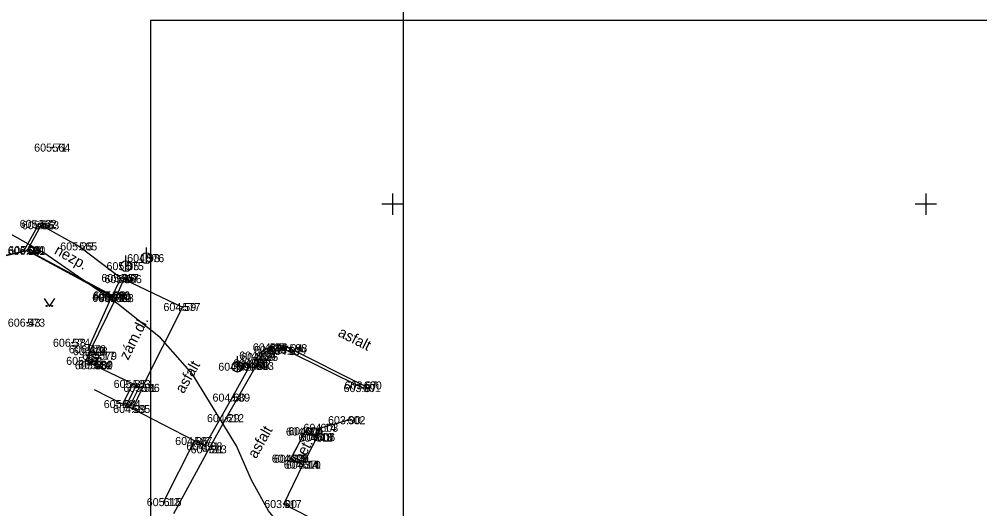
# Model space of a CAD drawing. Extents: x -844765 to -843273, y -997542 to -995529.
# Drawn here: x -843585 to -843494.9, y -997278.6 to -997232.7 of the extents above; entities that cross this region are included whole.
import ezdxf

# ---------------------------------------------------------------- set-up
doc = ezdxf.new("R2010")
doc.units = 0
for name, color, linetype in [('Benešův rám', 7, 'Continuous'), ('Betonový strop', 7, 'Continuous'), ('Dno', 7, 'Continuous'), ('Doplněk polohopisu', 7, 'Continuous'), ('Klenba', 7, 'Continuous'), ('Osa', 7, 'Continuous'), ('Rámeček', 7, 'Continuous'), ('Sítě podzemní nerozlišené', 7, 'Continuous'), ('Vrstva 63', 7, 'Continuous'), ('Výška', 7, 'Continuous'), ('Číslo bodu', 7, 'Continuous'), ('Řezy', 7, 'Continuous')]:
    doc.layers.add(name, color=color, linetype=linetype)

msp = doc.modelspace()

# ---------------------------------------------------------------- linework, layer by layer
at = {"layer": 'Benešův rám'}
msp.add_line((-843576.24, -997258.56), (-843575.92, -997258.82), dxfattribs=at)
for points in [[(-843575.92, -997258.82), (-843578.36, -997263.79), (-843578.74, -997264.7)], [(-843578.51, -997263.61), (-843576.3, -997258.66), (-843576.24, -997258.56)], [(-843570.49, -997279.01), (-843567.2, -997272.99), (-843565.58, -997270.07), (-843562.78, -997265.18), (-843563.22, -997264.93), (-843565.01, -997268.14), (-843567.6, -997272.71), (-843568.54, -997272.21)]]:
    msp.add_lwpolyline(points, dxfattribs=at)
at = {"layer": 'Betonový strop'}
for p, q in [((-843583.14, -997251.86), (-843584.552, -997254.39)), ((-843577.78, -997264.813), (-843578.615, -997264.4)), ((-843577.635, -997264.516), (-843578.487, -997264.095)), ((-843577.49, -997264.22), (-843578.36, -997263.79)), ((-843577.93, -997265.12), (-843577.49, -997264.22)), ((-843577.93, -997265.12), (-843578.74, -997264.7)), ((-843574.33, -997266.86), (-843577.93, -997265.12)), ((-843574.956, -997268.907), (-843574.016, -997266.997)), ((-843574.663, -997269.058), (-843573.713, -997267.128)), ((-843574.37, -997269.21), (-843573.412, -997267.263)), ((-843573.412, -997267.263), (-843573.48, -997267.23))]:
    msp.add_line(p, q, dxfattribs=at)
for points in [[(-843584.21, -997254.31), (-843582.91, -997251.99), (-843583.14, -997251.86)], [(-843582.91, -997251.99), (-843579.34, -997253.97), (-843575.45, -997256.93)], [(-843590.56, -997259.11), (-843589.27, -997256.78), (-843588.36, -997255.6), (-843586.7, -997254.89), (-843584.21, -997254.31), (-843576.24, -997258.56)], [(-843576.3, -997258.66), (-843584.21, -997254.4), (-843586.73, -997254.99), (-843588.3, -997255.64), (-843589.2, -997256.81), (-843590.49, -997259.15)], [(-843575.92, -997258.82), (-843575.16, -997257.04), (-843575.45, -997256.93), (-843576.24, -997258.56)], [(-843575.16, -997257.04), (-843569.66, -997259.65), (-843573.48, -997267.23)], [(-843559.65, -997263.51), (-843552.67, -997267)], [(-843577.93, -997265.12), (-843577.87, -997265.06), (-843577.49, -997264.22)], [(-843563.06, -997265.03), (-843562.56, -997264.2)], [(-843562.38, -997264.34), (-843562.78, -997265.18)], [(-843552.76, -997267.25), (-843559.76, -997263.78)], [(-843575.26, -997268.75), (-843574.33, -997266.86), (-843573.48, -997267.23)], [(-843557.04, -997271.85), (-843558.18, -997271.29), (-843559.53, -997273.88), (-843558.39, -997274.44)], [(-843558.39, -997274.42), (-843559.51, -997273.86), (-843558.15, -997271.33), (-843557.09, -997271.9)]]:
    msp.add_lwpolyline(points, dxfattribs=at)
for centre, radius, start, end in [((-843560.671, -997265.686), 2.404, 64.86792, 141.81058), ((-843560.717, -997265.71), 2.154, 63.61279, 140.51698)]:
    msp.add_arc(centre, radius, start, end, dxfattribs=at)
at = {"layer": 'Dno'}
msp.add_lwpolyline([(-843582.65, -997258.849), (-843582.15, -997259.599), (-843581.65, -997258.849)], dxfattribs=at)
for centre in [(-843582.4, -997259.549), (-843581.9, -997259.549)]:
    msp.add_circle(centre, 0.05, dxfattribs=at)
at = {"layer": 'Doplněk polohopisu'}
for p, q in [((-843573.06, -997255.57), (-843573.06, -997254.07)), ((-843574.97, -997256.32), (-843574.97, -997254.82)), ((-843564.52, -997265.75), (-843564.52, -997264.25))]:
    msp.add_line(p, q, dxfattribs=at)
for centre in [(-843573.06, -997255.07), (-843574.97, -997255.82), (-843564.52, -997265.25)]:
    msp.add_circle(centre, 0.5, dxfattribs=at)
at = {"layer": 'Klenba'}
for p, q in [((-843577.937, -997267.395), (-843575.26, -997268.75)), ((-843574.37, -997269.21), (-843575.26, -997268.75)), ((-843568.54, -997272.21), (-843574.37, -997269.21)), ((-843556.75, -997270.97), (-843554.2, -997270.26)), ((-843558.39, -997274.44), (-843557.04, -997271.85)), ((-843557.04, -997271.85), (-843556.75, -997270.97)), ((-843571.44, -997277.94), (-843568.54, -997272.21)), ((-843560.18, -997278.12), (-843558.39, -997274.44)), ((-843554.71, -997280.92), (-843560.18, -997278.12))]:
    msp.add_line(p, q, dxfattribs=at)
at = {"layer": 'Osa'}
msp.add_lwpolyline([(-843488.74, -997327.355), (-843502.42, -997320.345), (-843503.72, -997319.36), (-843508.85, -997314.12), (-843519.095, -997304.575), (-843522.13, -997301.975), (-843525.755, -997299.515), (-843535.535, -997294.28), (-843547.175, -997288.35), (-843559.45, -997281.385), (-843561.605, -997278.77), (-843563.2, -997275.885), (-843564.61, -997272.67), (-843568.725, -997265.945), (-843571.745, -997262.55), (-843575.655, -997259.4), (-843582.66, -997254.57), (-843594.613, -997247.845), (-843607.165, -997241.295), (-843613.085, -997237.56), (-843629.39, -997225.885), (-843652.733, -997208.733), (-843685.02, -997184.17)], dxfattribs=at)
at = {"layer": 'Rámeček'}
for p, q in [((-843550, -997249), (-843550, -997251)), ((-843500, -997249), (-843500, -997251)), ((-843549, -997250), (-843551, -997250)), ((-843499, -997250), (-843501, -997250))]:
    msp.add_line(p, q, dxfattribs=at)
at = {"layer": 'Sítě podzemní nerozlišené'}
for p, q in [((-843581.87, -997244.71), (-843581.92, -997244.66)), ((-843581.87, -997244.71), (-843581.92, -997244.76)), ((-843581.87, -997244.71), (-843581.82, -997244.66)), ((-843581.87, -997244.71), (-843581.82, -997244.76)), ((-843583.14, -997251.86), (-843583.19, -997251.81)), ((-843583.14, -997251.86), (-843583.19, -997251.91)), ((-843583.14, -997251.86), (-843583.09, -997251.81)), ((-843583.14, -997251.86), (-843583.09, -997251.91)), ((-843582.91, -997251.99), (-843582.96, -997251.94)), ((-843582.91, -997251.99), (-843582.96, -997252.04)), ((-843582.91, -997251.99), (-843582.86, -997251.94)), ((-843582.91, -997251.99), (-843582.86, -997252.04)), ((-843584.21, -997254.31), (-843584.26, -997254.26)), ((-843584.21, -997254.31), (-843584.26, -997254.36)), ((-843584.21, -997254.4), (-843584.26, -997254.35)), ((-843584.21, -997254.4), (-843584.26, -997254.45)), ((-843584.21, -997254.31), (-843584.16, -997254.26)), ((-843584.21, -997254.31), (-843584.16, -997254.36)), ((-843584.21, -997254.4), (-843584.16, -997254.35)), ((-843584.21, -997254.4), (-843584.16, -997254.45)), ((-843579.34, -997253.97), (-843579.39, -997253.92)), ((-843579.34, -997253.97), (-843579.39, -997254.02)), ((-843579.34, -997253.97), (-843579.29, -997253.92)), ((-843579.34, -997253.97), (-843579.29, -997254.02)), ((-843573.06, -997255.07), (-843573.11, -997255.02)), ((-843573.06, -997255.07), (-843573.11, -997255.12)), ((-843573.06, -997255.07), (-843573.01, -997255.02)), ((-843573.06, -997255.07), (-843573.01, -997255.12)), ((-843574.97, -997255.82), (-843575.02, -997255.77)), ((-843574.97, -997255.82), (-843575.02, -997255.87)), ((-843574.97, -997255.82), (-843574.92, -997255.77)), ((-843574.97, -997255.82), (-843574.92, -997255.87)), ((-843575.45, -997256.93), (-843575.5, -997256.88)), ((-843575.45, -997256.93), (-843575.5, -997256.98)), ((-843575.45, -997256.93), (-843575.4, -997256.88)), ((-843575.45, -997256.93), (-843575.4, -997256.98)), ((-843575.16, -997257.04), (-843575.21, -997256.99)), ((-843575.16, -997257.04), (-843575.21, -997257.09)), ((-843575.16, -997257.04), (-843575.11, -997256.99)), ((-843575.16, -997257.04), (-843575.11, -997257.09)), ((-843576.34, -997258.8), (-843576.39, -997258.75)), ((-843576.34, -997258.8), (-843576.39, -997258.85)), ((-843576.3, -997258.66), (-843576.35, -997258.61)), ((-843576.3, -997258.66), (-843576.35, -997258.71)), ((-843576.34, -997258.8), (-843576.29, -997258.75)), ((-843576.34, -997258.8), (-843576.29, -997258.85)), ((-843576.3, -997258.66), (-843576.25, -997258.61)), ((-843576.3, -997258.66), (-843576.25, -997258.71)), ((-843576.24, -997258.56), (-843576.29, -997258.51)), ((-843576.24, -997258.56), (-843576.29, -997258.61)), ((-843576.24, -997258.56), (-843576.19, -997258.51)), ((-843576.24, -997258.56), (-843576.19, -997258.61)), ((-843575.92, -997258.82), (-843575.97, -997258.77)), ((-843575.92, -997258.82), (-843575.97, -997258.87)), ((-843575.92, -997258.82), (-843575.87, -997258.77)), ((-843575.92, -997258.82), (-843575.87, -997258.87)), ((-843569.66, -997259.65), (-843569.71, -997259.6)), ((-843569.66, -997259.65), (-843569.71, -997259.7)), ((-843569.66, -997259.65), (-843569.61, -997259.6)), ((-843569.66, -997259.65), (-843569.61, -997259.7)), ((-843584.23, -997261.12), (-843584.28, -997261.07)), ((-843584.23, -997261.12), (-843584.28, -997261.17)), ((-843584.23, -997261.12), (-843584.18, -997261.07)), ((-843584.23, -997261.12), (-843584.18, -997261.17)), ((-843580, -997263), (-843580.05, -997262.95)), ((-843580, -997263), (-843580.05, -997263.05)), ((-843580, -997263), (-843579.95, -997262.95)), ((-843580, -997263), (-843579.95, -997263.05)), ((-843578.51, -997263.61), (-843578.56, -997263.56)), ((-843578.51, -997263.61), (-843578.56, -997263.66)), ((-843578.51, -997263.61), (-843578.46, -997263.56)), ((-843578.51, -997263.61), (-843578.46, -997263.66)), ((-843578.36, -997263.79), (-843578.41, -997263.74)), ((-843578.36, -997263.79), (-843578.31, -997263.74)), ((-843561.5, -997263.43), (-843561.55, -997263.38)), ((-843561.5, -997263.43), (-843561.55, -997263.48)), ((-843561.5, -997263.43), (-843561.45, -997263.38)), ((-843561.5, -997263.43), (-843561.45, -997263.48)), ((-843561.38, -997263.66), (-843561.43, -997263.61)), ((-843561.38, -997263.66), (-843561.43, -997263.71)), ((-843561.38, -997263.66), (-843561.33, -997263.61)), ((-843561.38, -997263.66), (-843561.33, -997263.71)), ((-843559.76, -997263.78), (-843559.81, -997263.73)), ((-843559.76, -997263.78), (-843559.71, -997263.73)), ((-843559.65, -997263.51), (-843559.7, -997263.46)), ((-843559.65, -997263.51), (-843559.7, -997263.56)), ((-843559.65, -997263.51), (-843559.6, -997263.46)), ((-843559.65, -997263.51), (-843559.6, -997263.56)), ((-843578.74, -997264.7), (-843578.79, -997264.65)), ((-843578.74, -997264.7), (-843578.69, -997264.65)), ((-843578.36, -997263.79), (-843578.41, -997263.84)), ((-843578.36, -997263.79), (-843578.31, -997263.84)), ((-843577.49, -997264.22), (-843577.54, -997264.17)), ((-843577.49, -997264.22), (-843577.54, -997264.27)), ((-843577.49, -997264.22), (-843577.44, -997264.17)), ((-843577.49, -997264.22), (-843577.44, -997264.27)), ((-843562.56, -997264.2), (-843562.61, -997264.15)), ((-843562.56, -997264.2), (-843562.61, -997264.25)), ((-843562.56, -997264.2), (-843562.51, -997264.15)), ((-843562.56, -997264.2), (-843562.51, -997264.25)), ((-843562.38, -997264.34), (-843562.43, -997264.29)), ((-843562.38, -997264.34), (-843562.43, -997264.39)), ((-843562.38, -997264.34), (-843562.33, -997264.29)), ((-843562.38, -997264.34), (-843562.33, -997264.39)), ((-843559.76, -997263.78), (-843559.81, -997263.83)), ((-843559.76, -997263.78), (-843559.71, -997263.83)), ((-843578.74, -997264.7), (-843578.79, -997264.75)), ((-843578.74, -997264.7), (-843578.69, -997264.75)), ((-843577.93, -997265.12), (-843577.98, -997265.07)), ((-843577.93, -997265.12), (-843577.98, -997265.17)), ((-843577.93, -997265.12), (-843577.88, -997265.07)), ((-843577.93, -997265.12), (-843577.88, -997265.17)), ((-843577.87, -997265.06), (-843577.92, -997265.01)), ((-843577.87, -997265.06), (-843577.92, -997265.11)), ((-843577.87, -997265.06), (-843577.82, -997265.01)), ((-843577.87, -997265.06), (-843577.82, -997265.11)), ((-843564.52, -997265.25), (-843564.57, -997265.2)), ((-843564.52, -997265.25), (-843564.57, -997265.3)), ((-843564.52, -997265.25), (-843564.47, -997265.2)), ((-843564.52, -997265.25), (-843564.47, -997265.3)), ((-843563.22, -997264.93), (-843563.27, -997264.88)), ((-843563.22, -997264.93), (-843563.27, -997264.98)), ((-843563.22, -997264.93), (-843563.17, -997264.88)), ((-843563.22, -997264.93), (-843563.17, -997264.98)), ((-843563.06, -997265.03), (-843563.11, -997264.98)), ((-843563.06, -997265.03), (-843563.11, -997265.08)), ((-843563.06, -997265.03), (-843563.01, -997264.98)), ((-843563.06, -997265.03), (-843563.01, -997265.08)), ((-843562.78, -997265.18), (-843562.83, -997265.13)), ((-843562.78, -997265.18), (-843562.83, -997265.23)), ((-843562.78, -997265.18), (-843562.73, -997265.13)), ((-843562.78, -997265.18), (-843562.73, -997265.23)), ((-843574.33, -997266.86), (-843574.38, -997266.81)), ((-843574.33, -997266.86), (-843574.38, -997266.91)), ((-843574.33, -997266.86), (-843574.28, -997266.81)), ((-843574.33, -997266.86), (-843574.28, -997266.91)), ((-843573.48, -997267.23), (-843573.53, -997267.18)), ((-843573.48, -997267.23), (-843573.53, -997267.28)), ((-843573.48, -997267.23), (-843573.43, -997267.18)), ((-843573.48, -997267.23), (-843573.43, -997267.28)), ((-843552.76, -997267.25), (-843552.81, -997267.2)), ((-843552.76, -997267.25), (-843552.81, -997267.3)), ((-843552.76, -997267.25), (-843552.71, -997267.2)), ((-843552.76, -997267.25), (-843552.71, -997267.3)), ((-843552.67, -997267), (-843552.72, -997266.95)), ((-843552.67, -997267), (-843552.72, -997267.05)), ((-843552.67, -997267), (-843552.62, -997266.95)), ((-843552.67, -997267), (-843552.62, -997267.05)), ((-843565.01, -997268.14), (-843565.06, -997268.09)), ((-843565.01, -997268.14), (-843565.06, -997268.19)), ((-843565.01, -997268.14), (-843564.96, -997268.09)), ((-843565.01, -997268.14), (-843564.96, -997268.19)), ((-843575.26, -997268.75), (-843575.31, -997268.7)), ((-843575.26, -997268.75), (-843575.31, -997268.8)), ((-843575.26, -997268.75), (-843575.21, -997268.7)), ((-843575.26, -997268.75), (-843575.21, -997268.8)), ((-843574.37, -997269.21), (-843574.42, -997269.16)), ((-843574.37, -997269.21), (-843574.32, -997269.16)), ((-843574.37, -997269.21), (-843574.42, -997269.26)), ((-843574.37, -997269.21), (-843574.32, -997269.26)), ((-843565.58, -997270.07), (-843565.63, -997270.02)), ((-843565.58, -997270.07), (-843565.53, -997270.02)), ((-843565.58, -997270.07), (-843565.63, -997270.12)), ((-843565.58, -997270.07), (-843565.53, -997270.12)), ((-843556.75, -997270.97), (-843556.8, -997270.92)), ((-843556.75, -997270.97), (-843556.7, -997270.92)), ((-843554.2, -997270.26), (-843554.25, -997270.21)), ((-843554.2, -997270.26), (-843554.25, -997270.31)), ((-843554.2, -997270.26), (-843554.15, -997270.21)), ((-843554.2, -997270.26), (-843554.15, -997270.31)), ((-843558.18, -997271.29), (-843558.23, -997271.24)), ((-843558.18, -997271.29), (-843558.23, -997271.34)), ((-843558.15, -997271.33), (-843558.2, -997271.28)), ((-843558.15, -997271.33), (-843558.2, -997271.38)), ((-843558.18, -997271.29), (-843558.13, -997271.24)), ((-843558.18, -997271.29), (-843558.13, -997271.34)), ((-843558.15, -997271.33), (-843558.1, -997271.28)), ((-843558.15, -997271.33), (-843558.1, -997271.38)), ((-843557.09, -997271.9), (-843557.14, -997271.85)), ((-843557.04, -997271.85), (-843557.09, -997271.8)), ((-843557.04, -997271.85), (-843557.09, -997271.9)), ((-843557.09, -997271.9), (-843557.04, -997271.85)), ((-843557.04, -997271.85), (-843556.99, -997271.8)), ((-843557.04, -997271.85), (-843556.99, -997271.9)), ((-843556.75, -997270.97), (-843556.8, -997271.02)), ((-843556.75, -997270.97), (-843556.7, -997271.02)), ((-843568.54, -997272.21), (-843568.59, -997272.16)), ((-843568.54, -997272.21), (-843568.59, -997272.26)), ((-843568.54, -997272.21), (-843568.49, -997272.16)), ((-843568.54, -997272.21), (-843568.49, -997272.26)), ((-843567.6, -997272.71), (-843567.65, -997272.66)), ((-843567.6, -997272.71), (-843567.65, -997272.76)), ((-843567.6, -997272.71), (-843567.55, -997272.66)), ((-843567.6, -997272.71), (-843567.55, -997272.76)), ((-843557.09, -997271.9), (-843557.14, -997271.95)), ((-843557.09, -997271.9), (-843557.04, -997271.95)), ((-843567.2, -997272.99), (-843567.25, -997272.94)), ((-843567.2, -997272.99), (-843567.25, -997273.04)), ((-843567.2, -997272.99), (-843567.15, -997272.94)), ((-843567.2, -997272.99), (-843567.15, -997273.04)), ((-843559.53, -997273.88), (-843559.58, -997273.83)), ((-843559.53, -997273.88), (-843559.58, -997273.93)), ((-843559.51, -997273.86), (-843559.56, -997273.81)), ((-843559.51, -997273.86), (-843559.56, -997273.91)), ((-843559.53, -997273.88), (-843559.48, -997273.83)), ((-843559.53, -997273.88), (-843559.48, -997273.93)), ((-843559.51, -997273.86), (-843559.46, -997273.81)), ((-843559.51, -997273.86), (-843559.46, -997273.91)), ((-843558.39, -997274.42), (-843558.44, -997274.37)), ((-843558.39, -997274.44), (-843558.44, -997274.39)), ((-843558.39, -997274.42), (-843558.44, -997274.47)), ((-843558.39, -997274.44), (-843558.44, -997274.49)), ((-843558.39, -997274.42), (-843558.34, -997274.37)), ((-843558.39, -997274.44), (-843558.34, -997274.39)), ((-843558.39, -997274.42), (-843558.34, -997274.47)), ((-843558.39, -997274.44), (-843558.34, -997274.49)), ((-843571.44, -997277.94), (-843571.49, -997277.89)), ((-843571.44, -997277.94), (-843571.49, -997277.99)), ((-843571.44, -997277.94), (-843571.39, -997277.89)), ((-843571.44, -997277.94), (-843571.39, -997277.99)), ((-843560.18, -997278.12), (-843560.23, -997278.07)), ((-843560.18, -997278.12), (-843560.23, -997278.17)), ((-843560.18, -997278.12), (-843560.13, -997278.07)), ((-843560.18, -997278.12), (-843560.13, -997278.17))]:
    msp.add_line(p, q, dxfattribs=at)
at = {"layer": 'Vrstva 63'}
for points in [[(-843738.967, -997297.121), (-843548.967, -997297.121), (-843548.967, -997154.621), (-843738.967, -997154.621)], [(-843572.683, -997375.3), (-843382.683, -997375.3), (-843382.683, -997232.8), (-843572.683, -997232.8)]]:
    msp.add_lwpolyline(points, close=True, dxfattribs=at)

# ---------------------------------------------------------------- texts
at = {"layer": 'Výška'}
for s, rotation, p in [('nezp.', 330.96502, (-843581.763, -997254.616)), ('zám.dl.', 63.25382, (-843574.772, -997264.695)), ('asfalt', 333.43495, (-843555.178, -997262.345)), ('asfalt', 60.45805, (-843569.567, -997267.83)), ('asfalt', 60.45805, (-843562.772, -997273.935)), ('bet.', 62.46987, (-843558.441, -997274.312))]:
    msp.add_text(s, height=1, rotation=rotation, dxfattribs=at).set_placement(p)
at = {"layer": 'Číslo bodu'}
for s, p in [('564', (-843581.87, -997245.085)), ('562', (-843583.14, -997252.235)), ('563', (-843582.91, -997252.365)), ('565', (-843579.34, -997254.345)), ('560', (-843584.21, -997254.685)), ('561', (-843584.21, -997254.775)), ('576', (-843573.06, -997255.445)), ('575', (-843574.97, -997256.195)), ('567', (-843575.45, -997257.305)), ('566', (-843575.16, -997257.415)), ('570', (-843576.3, -997259.035)), ('569', (-843576.24, -997258.935)), ('571', (-843576.34, -997259.175)), ('568', (-843575.92, -997259.195)), ('577', (-843569.66, -997260.025)), ('573', (-843584.23, -997261.495)), ('574', (-843580, -997263.375)), ('572', (-843578.51, -997263.985)), ('578', (-843578.36, -997264.165)), ('596', (-843561.5, -997263.805)), ('597', (-843561.38, -997264.035)), ('599', (-843559.76, -997264.155)), ('598', (-843559.65, -997263.885)), ('581', (-843578.74, -997265.075)), ('579', (-843577.49, -997264.595)), ('591', (-843563.22, -997265.305)), ('592', (-843563.06, -997265.405)), ('594', (-843562.56, -997264.575)), ('595', (-843562.38, -997264.715)), ('582', (-843577.93, -997265.495)), ('580', (-843577.87, -997265.435)), ('590', (-843564.52, -997265.625)), ('593', (-843562.78, -997265.555)), ('583', (-843574.33, -997267.235)), ('586', (-843573.48, -997267.605)), ('601', (-843552.76, -997267.625)), ('600', (-843552.67, -997267.375)), ('589', (-843565.01, -997268.515)), ('584', (-843575.26, -997269.125)), ('585', (-843574.37, -997269.585)), ('612', (-843565.58, -997270.445)), ('602', (-843554.2, -997270.635)), ('604', (-843558.18, -997271.665)), ('605', (-843558.15, -997271.705)), ('603', (-843556.75, -997271.345)), ('587', (-843568.54, -997272.585)), ('607', (-843557.09, -997272.275)), ('606', (-843557.04, -997272.225)), ('588', (-843567.6, -997273.085)), ('613', (-843567.2, -997273.365)), ('608', (-843559.53, -997274.255)), ('609', (-843559.51, -997274.235)), ('611', (-843558.39, -997274.795)), ('610', (-843558.39, -997274.815)), ('615', (-843571.44, -997278.315)), ('617', (-843560.18, -997278.495))]:
    msp.add_text(s, height=0.75, dxfattribs=at).set_placement(p)
at = {"layer": 'Řezy'}
for s, p in [('605.71', (-843583.577, -997245.085)), ('605.57', (-843584.935, -997252.235)), ('605.56', (-843584.726, -997252.365)), ('605.25', (-843581.135, -997254.345)), ('606.04', (-843586.058, -997254.775)), ('605.94', (-843586.008, -997254.685)), ('604.98', (-843574.858, -997255.445)), ('605.05', (-843576.798, -997256.195)), ('605.05', (-843577.278, -997257.305)), ('605.04', (-843576.988, -997257.415)), ('605.39', (-843578.098, -997259.035)), ('605.23', (-843578.035, -997258.935)), ('605.75', (-843578.135, -997259.175)), ('605.10', (-843577.535, -997259.195)), ('604.59', (-843571.458, -997260.025)), ('606.43', (-843586.046, -997261.495)), ('606.38', (-843581.816, -997263.375)), ('606.48', (-843580.326, -997263.985)), ('605.19', (-843579.946, -997264.165)), ('604.17', (-843563.083, -997263.805)), ('604.19', (-843562.966, -997264.035)), ('604.07', (-843561.588, -997264.155)), ('604.04', (-843561.478, -997263.885)), ('605.90', (-843580.571, -997265.075)), ('605.17', (-843579.073, -997264.595)), ('604.31', (-843564.927, -997265.305)), ('604.31', (-843564.767, -997265.405)), ('604.22', (-843564.355, -997264.575)), ('604.25', (-843564.175, -997264.715)), ('605.90', (-843579.761, -997265.495)), ('605.14', (-843579.453, -997265.435)), ('604.42', (-843566.315, -997265.625)), ('604.30', (-843564.608, -997265.555)), ('605.85', (-843576.125, -997267.235)), ('605.01', (-843575.219, -997267.605)), ('603.67', (-843554.576, -997267.625)), ('603.67', (-843554.486, -997267.375)), ('604.60', (-843566.858, -997268.515)), ('605.84', (-843577.055, -997269.125)), ('604.99', (-843576.171, -997269.585)), ('604.29', (-843567.378, -997270.445)), ('603.90', (-843556.031, -997270.635)), ('604.30', (-843559.978, -997271.705)), ('604.14', (-843559.763, -997271.665)), ('604.14', (-843558.333, -997271.345)), ('604.96', (-843570.359, -997272.585)), ('604.41', (-843558.797, -997272.275)), ('604.18', (-843558.623, -997272.225)), ('604.91', (-843569.309, -997273.085)), ('604.31', (-843568.907, -997273.365)), ('604.28', (-843561.305, -997274.235)), ('604.13', (-843561.113, -997274.255)), ('604.37', (-843560.185, -997274.795)), ('604.14', (-843559.973, -997274.815)), ('605.12', (-843573.023, -997278.315)), ('603.90', (-843562.011, -997278.495))]:
    msp.add_text(s, height=0.75, dxfattribs=at).set_placement(p)

doc.saveas('drawing.dxf')
